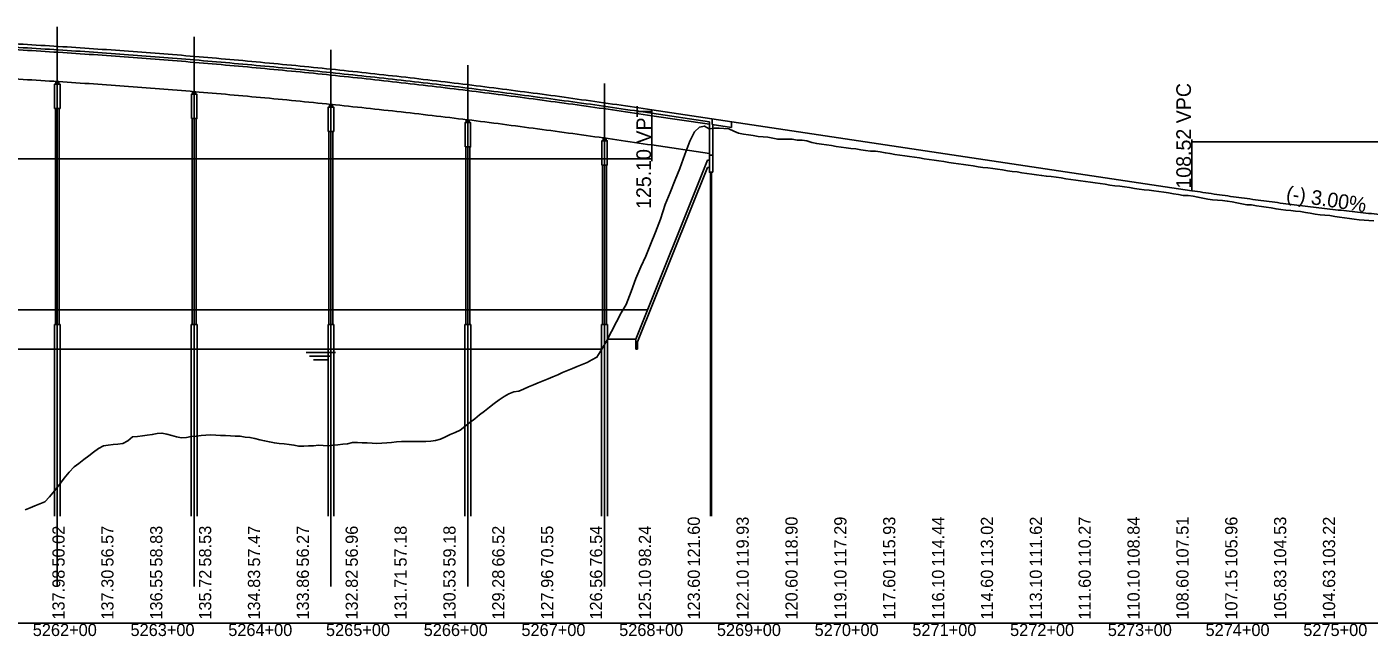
# Model space of a CAD drawing. Extents: x 2121671 to 2169879, y 557274 to 599957.
# Drawn here: x 2155728 to 2157102, y 579173 to 579797 of the extents above; entities that cross this region are included whole.
import ezdxf

# ---------------------------------------------------------------- set-up
doc = ezdxf.new("R2010")
doc.units = 0
for name, color, linetype in [('BR_CENTER LINES', 7, 'Continuous'), ('BR_CONCRETE', 7, 'Continuous'), ('BR_DETAILS', 7, 'Continuous'), ('BR_PRESTRESSED BEAM', 7, 'Continuous'), ('BR_STRUCTURAL STEEL', 7, 'Continuous'), ('RD_DDB_GradeTX', 7, 'Continuous'), ('RD_DDB_Profile_Elev', 7, 'Continuous'), ('RD_DDB_Profile_EX', 7, 'Continuous'), ('RD_DDB_Profile_PR', 7, 'Continuous'), ('RD_DDB_StaTX', 7, 'Continuous'), ('RD_DDB_StripGrade', 7, 'Continuous'), ('RD_DDB_VCLbl', 7, 'Continuous'), ('RD_GPK_Profile_Cell', 7, 'Continuous')]:
    doc.layers.add(name, color=color, linetype=linetype)

msp = doc.modelspace()

# ---------------------------------------------------------------- linework, layer by layer
at = {"layer": 'BR_CENTER LINES'}
for p, q in [((2155759.4, 579224.3), (2155759.4, 579797.3)), ((2155899.4, 579224.3), (2155899.4, 579787)), ((2156039.4, 579224.3), (2156039.4, 579773.9)), ((2156179.4, 579224.3), (2156179.4, 579758.1)), ((2156319.4, 579224.3), (2156319.4, 579739.4))]:
    msp.add_line(p, q, dxfattribs=at)
at = {"layer": 'BR_CONCRETE'}
for p, q in [((2155757.4, 579713.7), (2155757.4, 579492.4)), ((2155761.4, 579713.7), (2155761.4, 579492.4)), ((2155897.4, 579703.3), (2155897.4, 579492.4)), ((2155901.4, 579703.3), (2155901.4, 579492.4)), ((2156367.9, 579708.8), (2156426.6, 579700)), ((2156426.6, 579665.9), (2156426.6, 579700)), ((2156429.4, 579697.3), (2156429.4, 579703.1)), ((2156429.4, 579697.3), (2156449.4, 579694.3)), ((2156430.1, 579665.9), (2156430.1, 579697.2)), ((2156449.4, 579694.3), (2156449.4, 579700.1)), ((2156037.4, 579690.2), (2156037.4, 579492.4)), ((2156041.4, 579690.2), (2156041.4, 579492.4)), ((2156177.4, 579674.3), (2156177.4, 579492.4)), ((2156181.4, 579674.3), (2156181.4, 579492.4)), ((2156317.4, 579655.7), (2156317.4, 579492.4)), ((2156321.4, 579655.7), (2156321.4, 579492.4)), ((2155756.4, 579492.4), (2155756.4, 579296.1)), ((2155756.4, 579492.4), (2155762.4, 579492.4)), ((2155762.4, 579492.4), (2155762.4, 579296.1)), ((2155896.4, 579492.4), (2155896.4, 579296.1)), ((2155896.4, 579492.4), (2155902.4, 579492.4)), ((2155902.4, 579492.4), (2155902.4, 579296.1)), ((2156036.4, 579492.4), (2156036.4, 579296.1)), ((2156036.4, 579492.4), (2156042.4, 579492.4)), ((2156042.4, 579492.4), (2156042.4, 579296.1)), ((2156176.4, 579492.4), (2156176.4, 579296.1)), ((2156176.4, 579492.4), (2156182.4, 579492.4)), ((2156182.4, 579492.4), (2156182.4, 579296.1)), ((2156316.4, 579492.4), (2156316.4, 579296.1)), ((2156316.4, 579492.4), (2156322.4, 579492.4)), ((2156322.4, 579492.4), (2156322.4, 579296.1))]:
    msp.add_line(p, q, dxfattribs=at)
for points in [[(2155756.7, 579713.7), (2155762.2, 579713.7), (2155762.2, 579738.7), (2155756.7, 579738.7)], [(2155896.7, 579703.3), (2155902.2, 579703.3), (2155902.2, 579728.3), (2155896.7, 579728.3)], [(2156036.7, 579690.2), (2156042.2, 579690.2), (2156042.2, 579715.2), (2156036.7, 579715.2)], [(2156176.7, 579674.3), (2156182.2, 579674.3), (2156182.2, 579699.3), (2156176.7, 579699.3)], [(2156316.7, 579655.7), (2156322.2, 579655.7), (2156322.2, 579680.7), (2156316.7, 579680.7)], [(2156430.1, 579648.4), (2156426.6, 579648.4), (2156426.6, 579665.9), (2156430.1, 579665.9)]]:
    msp.add_lwpolyline(points, close=True, dxfattribs=at)
msp.add_spline([(2154567.9, 579748.7), (2154603.9, 579752.4), (2154639.9, 579755.9), (2154675.9, 579759.3), (2154711.9, 579762.4), (2154747.9, 579765.4), (2154783.9, 579768.2), (2154819.9, 579770.8), (2154855.9, 579773.2), (2154891.9, 579775.5), (2154927.9, 579777.5), (2154963.9, 579779.4), (2154999.9, 579781.1), (2155035.9, 579782.6), (2155071.9, 579783.9), (2155107.9, 579785), (2155143.9, 579786), (2155179.9, 579786.8), (2155215.9, 579787.3), (2155251.9, 579787.7), (2155287.9, 579787.9), (2155323.9, 579788), (2155359.9, 579787.8), (2155395.9, 579787.5), (2155431.9, 579787), (2155467.9, 579786.3), (2155503.9, 579785.4), (2155539.9, 579784.3), (2155575.9, 579783), (2155611.9, 579781.6), (2155647.9, 579780), (2155683.9, 579778.2), (2155719.9, 579776.2), (2155755.9, 579774), (2155791.9, 579771.6), (2155827.9, 579769.1), (2155863.9, 579766.3), (2155899.9, 579763.4), (2155935.9, 579760.3), (2155971.9, 579757), (2156007.9, 579753.6), (2156043.9, 579749.9), (2156079.9, 579746.1), (2156115.9, 579742.1), (2156151.9, 579737.9), (2156187.9, 579733.5), (2156223.9, 579728.9), (2156259.9, 579724.1), (2156295.9, 579719.2), (2156331.9, 579714.1), (2156367.9, 579708.8)], degree=3, dxfattribs=at)
at = {"layer": 'BR_DETAILS'}
for p, q in [((2156351.2, 579477.4), (2156424.6, 579660.9)), ((2156426.6, 579660.9), (2156424.6, 579660.9)), ((2156353.2, 579474.9), (2156424.6, 579653.4)), ((2156426.6, 579653.4), (2156424.6, 579653.4)), ((2156351.2, 579477.4), (2156322.5, 579477.4)), ((2156351.2, 579477.4), (2156351.2, 579467.4)), ((2156351.2, 579467.4), (2156353.2, 579467.4)), ((2156353.2, 579467.4), (2156353.2, 579474.9))]:
    msp.add_line(p, q, dxfattribs=at)
for points in [[(2155757.9, 579741.2), (2155758.9, 579741.2), (2155758.9, 579738.7), (2155757.9, 579738.7)], [(2155759.9, 579741.2), (2155760.9, 579741.2), (2155760.9, 579738.7), (2155759.9, 579738.7)], [(2155897.9, 579730.8), (2155898.9, 579730.8), (2155898.9, 579728.3), (2155897.9, 579728.3)], [(2155899.9, 579730.8), (2155900.9, 579730.8), (2155900.9, 579728.3), (2155899.9, 579728.3)], [(2156037.9, 579717.7), (2156038.9, 579717.7), (2156038.9, 579715.2), (2156037.9, 579715.2)], [(2156039.9, 579717.7), (2156040.9, 579717.7), (2156040.9, 579715.2), (2156039.9, 579715.2)], [(2156177.9, 579701.8), (2156178.9, 579701.8), (2156178.9, 579699.3), (2156177.9, 579699.3)], [(2156179.9, 579701.8), (2156180.9, 579701.8), (2156180.9, 579699.3), (2156179.9, 579699.3)], [(2156317.9, 579683.2), (2156318.9, 579683.2), (2156318.9, 579680.7), (2156317.9, 579680.7)], [(2156319.9, 579683.2), (2156320.9, 579683.2), (2156320.9, 579680.7), (2156319.9, 579680.7)]]:
    msp.add_lwpolyline(points, close=True, dxfattribs=at)
at = {"layer": 'BR_PRESTRESSED BEAM'}
for p, q in [((2156367.9, 579706.3), (2156426.6, 579697.5)), ((2156367.9, 579676.3), (2156426.6, 579667.5))]:
    msp.add_line(p, q, dxfattribs=at)
for points in [[(2154567.9, 579746.2), (2154603.9, 579749.9), (2154639.9, 579753.4), (2154675.9, 579756.8), (2154711.9, 579759.9), (2154747.9, 579762.9), (2154783.9, 579765.7), (2154819.9, 579768.3), (2154855.9, 579770.7), (2154891.9, 579773), (2154927.9, 579775), (2154963.9, 579776.9), (2154999.9, 579778.6), (2155035.9, 579780.1), (2155071.9, 579781.4), (2155107.9, 579782.5), (2155143.9, 579783.5), (2155179.9, 579784.3), (2155215.9, 579784.8), (2155251.9, 579785.2), (2155287.9, 579785.4), (2155323.9, 579785.5), (2155359.9, 579785.3), (2155395.9, 579785), (2155431.9, 579784.5), (2155467.9, 579783.8), (2155503.9, 579782.9), (2155539.9, 579781.8), (2155575.9, 579780.5), (2155611.9, 579779.1), (2155647.9, 579777.5), (2155683.9, 579775.7), (2155719.9, 579773.7), (2155755.9, 579771.5), (2155791.9, 579769.1), (2155827.9, 579766.6), (2155863.9, 579763.8), (2155899.9, 579760.9), (2155935.9, 579757.8), (2155971.9, 579754.5), (2156007.9, 579751.1), (2156043.9, 579747.4), (2156079.9, 579743.6), (2156115.9, 579739.6), (2156151.9, 579735.4), (2156187.9, 579731), (2156223.9, 579726.4), (2156259.9, 579721.6), (2156295.9, 579716.7), (2156331.9, 579711.6), (2156367.9, 579706.3)], [(2154567.9, 579716.2), (2154603.9, 579719.9), (2154639.9, 579723.4), (2154675.9, 579726.8), (2154711.9, 579729.9), (2154747.9, 579732.9), (2154783.9, 579735.7), (2154819.9, 579738.3), (2154855.9, 579740.7), (2154891.9, 579743), (2154927.9, 579745), (2154963.9, 579746.9), (2154999.9, 579748.6), (2155035.9, 579750.1), (2155071.9, 579751.4), (2155107.9, 579752.5), (2155143.9, 579753.5), (2155179.9, 579754.3), (2155215.9, 579754.8), (2155251.9, 579755.2), (2155287.9, 579755.4), (2155323.9, 579755.5), (2155359.9, 579755.3), (2155395.9, 579755), (2155431.9, 579754.5), (2155467.9, 579753.8), (2155503.9, 579752.9), (2155539.9, 579751.8), (2155575.9, 579750.5), (2155611.9, 579749.1), (2155647.9, 579747.5), (2155683.9, 579745.7), (2155719.9, 579743.7), (2155755.9, 579741.5), (2155791.9, 579739.1), (2155827.9, 579736.6), (2155863.9, 579733.8), (2155899.9, 579730.9), (2155935.9, 579727.8), (2155971.9, 579724.5), (2156007.9, 579721.1), (2156043.9, 579717.4), (2156079.9, 579713.6), (2156115.9, 579709.6), (2156151.9, 579705.4), (2156187.9, 579701), (2156223.9, 579696.4), (2156259.9, 579691.6), (2156295.9, 579686.7), (2156331.9, 579681.6), (2156367.9, 579676.3)]]:
    msp.add_spline(points, degree=3, dxfattribs=at)
at = {"layer": 'BR_STRUCTURAL STEEL'}
for p, q in [((2156427.8, 579648.4), (2156427.8, 579296.1)), ((2156428.9, 579648.4), (2156428.9, 579296.1))]:
    msp.add_line(p, q, dxfattribs=at)
at = {"layer": 'RD_DDB_Profile_Elev'}
for p, q in [((2155599.4, 579507.4), (2156363.2, 579507.4)), ((2151953.5, 579467.4), (2156316.6, 579467.4)), ((2156013.9, 579463.7), (2156043.9, 579463.7)), ((2156017.6, 579459.9), (2156040.1, 579459.9)), ((2156021.4, 579456.2), (2156036.4, 579456.2))]:
    msp.add_line(p, q, dxfattribs=at)
at = {"layer": 'RD_DDB_Profile_EX'}
for points in [[(2156221.5, 579421.5), (2156226.5, 579423.7), (2156231.5, 579424.3), (2156236.5, 579426.4), (2156241.5, 579428.5), (2156246.5, 579430.6), (2156251.5, 579432.7), (2156256.5, 579434.8), (2156261.5, 579436.9), (2156266.5, 579439), (2156271.5, 579441.1), (2156276.5, 579443.2), (2156281.5, 579445.3), (2156286.5, 579447.3), (2156291.5, 579449.4), (2156296.5, 579451.5), (2156301.5, 579453.6), (2156306.5, 579456.2), (2156311.5, 579458.9), (2156316.5, 579467.2), (2156321.5, 579475.4), (2156326.5, 579485.2), (2156331.5, 579495.3), (2156336.5, 579504.6), (2156341.5, 579513), (2156346.5, 579526.4), (2156351.5, 579539.5), (2156356.5, 579551.5), (2156361.5, 579562.5), (2156366.5, 579574.4), (2156371.5, 579586.9), (2156376.5, 579600.3), (2156381.5, 579615.2), (2156386.5, 579627.7), (2156391.5, 579640.7), (2156396.5, 579652.2), (2156401.5, 579666.6), (2156406.5, 579680.3), (2156411.5, 579689.7), (2156416.5, 579694.5), (2156421.5, 579695.6), (2156426.5, 579692.9), (2156431.5, 579693.4), (2156436.5, 579693.6), (2156441.5, 579693.1), (2156446.5, 579693), (2156451.5, 579690.5), (2156456.5, 579688.3), (2156461.5, 579687.4), (2156466.5, 579686.7), (2156471.5, 579685.9), (2156476.5, 579685), (2156481.5, 579684.7), (2156486.5, 579684.3), (2156491.5, 579683.4), (2156496.5, 579682.1), (2156501.5, 579682.1), (2156506.5, 579682.2), (2156511.5, 579682.1), (2156516.5, 579681.4), (2156521.5, 579681.1), (2156526.5, 579680.4), (2156531.5, 579678.9), (2156536.5, 579677.8), (2156541.5, 579677.1), (2156546.5, 579676.4), (2156551.5, 579675.7), (2156556.5, 579674.6), (2156561.5, 579674.2), (2156566.5, 579673.5), (2156571.5, 579672.8), (2156576.5, 579672.2), (2156581.5, 579671.5), (2156586.5, 579670.6), (2156591.5, 579670), (2156596.5, 579670), (2156601.5, 579669.2), (2156606.5, 579668.4), (2156611.5, 579667.5), (2156616.5, 579666.7), (2156621.5, 579665.9), (2156626.5, 579665.2), (2156631.5, 579664.4), (2156636.5, 579663.7), (2156641.5, 579663), (2156646.5, 579662.3), (2156651.5, 579661.6), (2156656.5, 579660.8), (2156661.5, 579660), (2156666.5, 579659.3), (2156671.5, 579658.5), (2156676.5, 579657.8), (2156681.5, 579657), (2156686.5, 579656.3), (2156691.5, 579655.5), (2156696.5, 579654.8), (2156701.5, 579654.1), (2156706.5, 579653.4), (2156711.5, 579652.8), (2156716.5, 579652.1), (2156721.5, 579651.4)], [(2156721.5, 579651.4), (2156726.5, 579650.8), (2156731.5, 579650), (2156736.5, 579649.3), (2156741.5, 579648.7), (2156746.5, 579647.9), (2156751.5, 579647.2), (2156756.5, 579646.4), (2156761.5, 579645.7), (2156766.5, 579645.2), (2156771.5, 579644.3), (2156776.5, 579644), (2156781.5, 579643.3), (2156786.5, 579642.6), (2156791.5, 579641.8), (2156796.5, 579641), (2156801.5, 579640.2), (2156806.5, 579639.5), (2156811.5, 579639), (2156816.5, 579638.4), (2156821.5, 579637.7), (2156826.5, 579636.9), (2156831.5, 579636.1), (2156836.5, 579635.2), (2156841.5, 579634.6), (2156846.5, 579634.3), (2156851.5, 579633.5), (2156856.5, 579632.7), (2156861.5, 579631.9), (2156866.5, 579631.2), (2156871.5, 579630.5), (2156876.5, 579629.9), (2156881.5, 579629.4), (2156886.5, 579628.8), (2156891.5, 579628), (2156896.5, 579627.2), (2156901.5, 579626.4), (2156906.5, 579625.6), (2156911.5, 579624.7), (2156916.5, 579624.6), (2156921.5, 579623.8), (2156926.5, 579623), (2156931.5, 579622), (2156936.5, 579621), (2156941.5, 579620.2), (2156946.5, 579619.7), (2156951.5, 579619.3), (2156956.5, 579618.9), (2156961.5, 579618), (2156966.5, 579617), (2156971.5, 579615.9), (2156976.5, 579615.1), (2156981.5, 579614.9), (2156986.5, 579614.1), (2156991.5, 579613.4), (2156996.5, 579612.6), (2157001.5, 579611.8), (2157006.5, 579610.9), (2157011.5, 579610.3), (2157016.5, 579609.6), (2157021.5, 579609.2), (2157026.5, 579608.7), (2157031.5, 579608.1), (2157036.5, 579607.3), (2157041.5, 579606.4), (2157046.5, 579605.6), (2157051.5, 579604.8), (2157056.5, 579604.3), (2157061.5, 579604), (2157066.5, 579603.1), (2157071.5, 579602.4), (2157076.5, 579601.7), (2157081.5, 579601), (2157086.5, 579600.3), (2157091.5, 579599.6), (2157096.5, 579599.2), (2157101.5, 579599), (2157106.5, 579598.5)], [(2155726.5, 579302.8), (2155731.5, 579304.7), (2155736.5, 579306.7), (2155741.5, 579308.7), (2155746.5, 579310.9), (2155751.5, 579315.9), (2155756.5, 579322.3), (2155761.5, 579328.7), (2155766.5, 579335.1), (2155771.5, 579341.4), (2155776.5, 579346.7), (2155781.5, 579350.3), (2155786.5, 579354.1), (2155791.5, 579357.9), (2155796.5, 579361.7), (2155801.5, 579365.5), (2155806.5, 579368.3), (2155811.5, 579368.9), (2155816.5, 579369.5), (2155821.5, 579370.1), (2155826.5, 579370.7), (2155831.5, 579373.4), (2155836.5, 579377.3), (2155841.5, 579377.9), (2155846.5, 579378.5), (2155851.5, 579379.1), (2155856.5, 579379.7), (2155861.5, 579380.8), (2155866.5, 579381.3), (2155871.5, 579380.1), (2155876.5, 579378.8), (2155881.5, 579377.6), (2155886.5, 579376.3), (2155891.5, 579376.9), (2155896.5, 579377.9), (2155901.5, 579378.3), (2155906.5, 579378.7), (2155911.5, 579379.1), (2155916.5, 579379.5), (2155921.5, 579379.3), (2155926.5, 579379), (2155931.5, 579378.8), (2155936.5, 579378.5), (2155941.5, 579378.3), (2155946.5, 579378), (2155951.5, 579377.2), (2155956.5, 579376.9), (2155961.5, 579375.7), (2155966.5, 579374.5), (2155971.5, 579373.4), (2155976.5, 579372.2), (2155981.5, 579371.3), (2155986.5, 579370.8), (2155991.5, 579370.2), (2155996.5, 579369.7), (2156001.5, 579369.1), (2156006.5, 579367.8), (2156011.5, 579367.8), (2156016.5, 579368.1), (2156021.5, 579368.4), (2156026.5, 579368.8), (2156031.5, 579368.7), (2156036.5, 579368.3), (2156041.5, 579368.9), (2156046.5, 579369.4), (2156051.5, 579369.9), (2156056.5, 579370.4), (2156061.5, 579371.6), (2156066.5, 579371.7), (2156071.5, 579371.4), (2156076.5, 579371.2), (2156081.5, 579370.9), (2156086.5, 579370.8), (2156091.5, 579371), (2156096.5, 579371.4), (2156101.5, 579371.8), (2156106.5, 579372.2), (2156111.5, 579372.6), (2156116.5, 579372.7), (2156121.5, 579372.7), (2156126.5, 579372.7), (2156131.5, 579372.8), (2156136.5, 579372.8), (2156141.5, 579372.9), (2156146.5, 579373.8), (2156151.5, 579375.2), (2156156.5, 579377.5), (2156161.5, 579379.8), (2156166.5, 579382), (2156171.5, 579384.4), (2156176.5, 579388), (2156181.5, 579392), (2156186.5, 579396), (2156191.5, 579400), (2156196.5, 579403.9), (2156201.5, 579407.8), (2156206.5, 579411.7), (2156211.5, 579415.5), (2156216.5, 579418.6), (2156221.5, 579421.5)]]:
    msp.add_lwpolyline(points, dxfattribs=at)
at = {"layer": 'RD_DDB_Profile_PR'}
msp.add_line((2156367.9, 579712.3), (2156920.4, 579629.4), dxfattribs=at)
for points in [[(2154567.9, 579752.2), (2154603.9, 579756), (2154639.9, 579759.5), (2154675.9, 579762.8), (2154711.9, 579766), (2154747.9, 579769), (2154783.9, 579771.8), (2154819.9, 579774.4), (2154855.9, 579776.8), (2154891.9, 579779), (2154927.9, 579781.1), (2154963.9, 579782.9), (2154999.9, 579784.6), (2155035.9, 579786.1), (2155071.9, 579787.4), (2155107.9, 579788.6), (2155143.9, 579789.5), (2155179.9, 579790.3), (2155215.9, 579790.9), (2155251.9, 579791.3), (2155287.9, 579791.5), (2155323.9, 579791.5), (2155359.9, 579791.4), (2155395.9, 579791), (2155431.9, 579790.5), (2155467.9, 579789.8), (2155503.9, 579788.9), (2155539.9, 579787.8), (2155575.9, 579786.6), (2155611.9, 579785.1), (2155647.9, 579783.5), (2155683.9, 579781.7), (2155719.9, 579779.7), (2155755.9, 579777.5), (2155791.9, 579775.2), (2155827.9, 579772.6), (2155863.9, 579769.9), (2155899.9, 579767), (2155935.9, 579763.9), (2155971.9, 579760.6), (2156007.9, 579757.1), (2156043.9, 579753.5), (2156079.9, 579749.6), (2156115.9, 579745.6), (2156151.9, 579741.4), (2156187.9, 579737), (2156223.9, 579732.4), (2156259.9, 579727.7), (2156295.9, 579722.7), (2156331.9, 579717.6), (2156367.9, 579712.3)], [(2156920.4, 579629.4), (2156931.7, 579627.8), (2156943, 579626.1), (2156954.3, 579624.5), (2156965.6, 579622.9), (2156976.9, 579621.4), (2156988.2, 579619.8), (2156999.5, 579618.3), (2157010.8, 579616.9), (2157022.1, 579615.4), (2157033.4, 579614), (2157044.7, 579612.7), (2157056, 579611.3), (2157067.3, 579610), (2157078.6, 579608.8), (2157089.9, 579607.5), (2157101.2, 579606.3), (2157112.5, 579605.1), (2157123.8, 579604), (2157135.1, 579602.9), (2157146.4, 579601.8), (2157157.7, 579600.7), (2157169, 579599.7), (2157180.3, 579598.7), (2157191.6, 579597.7), (2157202.9, 579596.8), (2157214.2, 579595.9), (2157225.5, 579595), (2157236.8, 579594.2), (2157248.1, 579593.4), (2157259.4, 579592.6), (2157270.7, 579591.9), (2157282, 579591.2), (2157293.3, 579590.5), (2157304.6, 579589.8), (2157315.9, 579589.2), (2157327.2, 579588.6), (2157338.5, 579588.1), (2157349.8, 579587.5), (2157361.1, 579587), (2157372.4, 579586.6), (2157383.7, 579586.1), (2157395, 579585.7), (2157406.3, 579585.4), (2157417.6, 579585), (2157428.9, 579584.7), (2157440.2, 579584.4), (2157451.5, 579584.2), (2157462.8, 579584), (2157474.1, 579583.8), (2157485.4, 579583.6)]]:
    msp.add_spline(points, degree=3, dxfattribs=at)
at = {"layer": 'RD_DDB_VCLbl'}
for p, q in [((2156367.9, 579659.8), (2156367.9, 579712.3)), ((2156920.4, 579681.9), (2156920.4, 579629.4)), ((2156920.4, 579679.4), (2157485.4, 579679.4)), ((2154567.9, 579662.3), (2156367.9, 579662.3))]:
    msp.add_line(p, q, dxfattribs=at)
at = {"layer": 'RD_GPK_Profile_Cell'}
msp.add_line((2151067.9, 579186.8), (2157367.9, 579186.8), dxfattribs=at)

# ---------------------------------------------------------------- texts
at = {"layer": 'RD_DDB_GradeTX'}
msp.add_text('(-) 3.00%', height=15, rotation=351.4692, dxfattribs=at).set_placement((2157016.1, 579619.6))
at = {"layer": 'RD_DDB_StaTX'}
for s, p in [('5262+00', (2155734.3, 579173.5)), ('5263+00', (2155834.3, 579173.5)), ('5264+00', (2155934.3, 579173.5)), ('5265+00', (2156034.3, 579173.5)), ('5266+00', (2156134.3, 579173.5)), ('5267+00', (2156234.3, 579173.5)), ('5268+00', (2156334.3, 579173.5)), ('5269+00', (2156434.3, 579173.5)), ('5270+00', (2156534.3, 579173.5)), ('5271+00', (2156634.3, 579173.5)), ('5272+00', (2156734.3, 579173.5)), ('5273+00', (2156834.3, 579173.5)), ('5274+00', (2156934.3, 579173.5)), ('5275+00', (2157034.3, 579173.5))]:
    msp.add_text(s, height=12.5, dxfattribs=at).set_placement(p)
at = {"layer": 'RD_DDB_StripGrade'}
for s, height, p in [('108.52 VPC', 15, (2156919.4, 579631.6)), ('125.10 VPT', 15, (2156366.9, 579610.8)), ('50.02', 12.5, (2155766.9, 579244.6)), ('56.57', 12.5, (2155816.9, 579244.6)), ('58.83', 12.5, (2155866.9, 579244.6)), ('58.53', 12.5, (2155916.9, 579244.6)), ('57.47', 12.5, (2155966.9, 579244.6)), ('56.27', 12.5, (2156016.9, 579244.6)), ('56.96', 12.5, (2156066.9, 579244.6)), ('57.18', 12.5, (2156116.9, 579244.6)), ('59.18', 12.5, (2156166.9, 579244.6)), ('66.52', 12.5, (2156216.9, 579244.6)), ('70.55', 12.5, (2156266.9, 579244.6)), ('76.54', 12.5, (2156316.9, 579244.6)), ('98.24', 12.5, (2156366.9, 579244.6)), ('121.60', 12.5, (2156416.9, 579244.6)), ('119.93', 12.5, (2156466.9, 579244.6)), ('118.90', 12.5, (2156516.9, 579244.6)), ('117.29', 12.5, (2156566.9, 579244.6)), ('115.93', 12.5, (2156616.9, 579244.6)), ('114.44', 12.5, (2156666.9, 579244.6)), ('113.02', 12.5, (2156716.9, 579244.6)), ('111.62', 12.5, (2156766.9, 579244.6)), ('110.27', 12.5, (2156816.9, 579244.6)), ('108.84', 12.5, (2156866.9, 579244.6)), ('107.51', 12.5, (2156916.9, 579244.6)), ('105.96', 12.5, (2156966.9, 579244.6)), ('104.53', 12.5, (2157016.9, 579244.6)), ('103.22', 12.5, (2157066.9, 579244.6)), ('137.98', 12.5, (2155766.9, 579190.3)), ('137.30', 12.5, (2155816.9, 579190.3)), ('136.55', 12.5, (2155866.9, 579190.3)), ('135.72', 12.5, (2155916.9, 579190.3)), ('134.83', 12.5, (2155966.9, 579190.3)), ('133.86', 12.5, (2156016.9, 579190.3)), ('132.82', 12.5, (2156066.9, 579190.3)), ('131.71', 12.5, (2156116.9, 579190.3)), ('130.53', 12.5, (2156166.9, 579190.3)), ('129.28', 12.5, (2156216.9, 579190.3)), ('127.96', 12.5, (2156266.9, 579190.3)), ('126.56', 12.5, (2156316.9, 579190.3)), ('125.10', 12.5, (2156366.9, 579190.3)), ('123.60', 12.5, (2156416.9, 579190.3)), ('122.10', 12.5, (2156466.9, 579190.3)), ('120.60', 12.5, (2156516.9, 579190.3)), ('119.10', 12.5, (2156566.9, 579190.3)), ('117.60', 12.5, (2156616.9, 579190.3)), ('116.10', 12.5, (2156666.9, 579190.3)), ('114.60', 12.5, (2156716.9, 579190.3)), ('113.10', 12.5, (2156766.9, 579190.3)), ('111.60', 12.5, (2156816.9, 579190.3)), ('110.10', 12.5, (2156866.9, 579190.3)), ('108.60', 12.5, (2156916.9, 579190.3)), ('107.15', 12.5, (2156966.9, 579190.3)), ('105.83', 12.5, (2157016.9, 579190.3)), ('104.63', 12.5, (2157066.9, 579190.3))]:
    msp.add_text(s, height=height, rotation=90, dxfattribs=at).set_placement(p)

doc.saveas('drawing.dxf')
